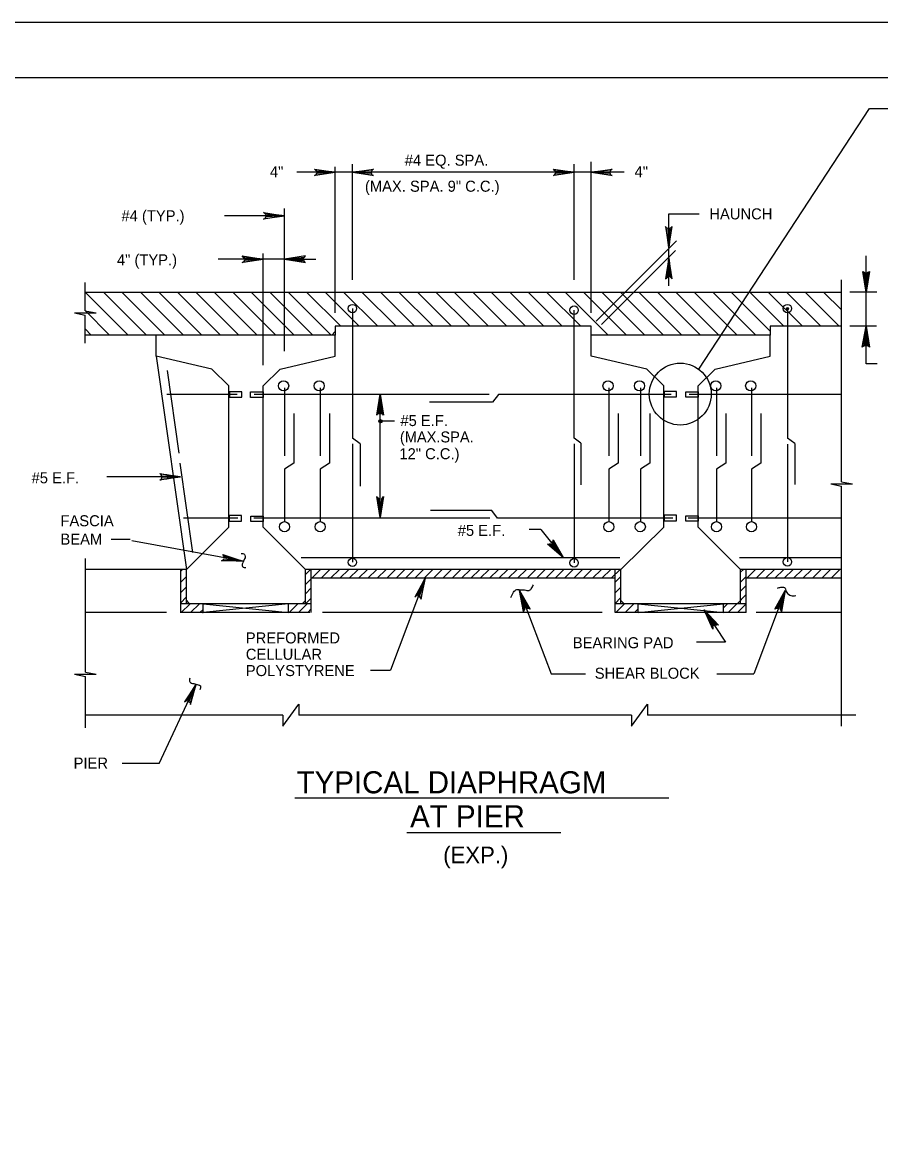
# Model space of a CAD drawing. Extents: x 639980 to 641204, y 298038 to 300414.
# Drawn here: x 640308.1 to 640541.7, y 300111.5 to 300413.8 of the extents above; entities that cross this region are included whole.
import ezdxf

# ---------------------------------------------------------------- set-up
doc = ezdxf.new("R2010")
doc.units = 0
doc.layers.add('2', color=7, linetype='Continuous')
doc.layers.add('PLT-BNDY', color=7, linetype='Continuous')

msp = doc.modelspace()

# ---------------------------------------------------------------- linework, layer by layer
at = {"layer": '2'}
for p, q in [((640020.31, 300398.78), (640806.31, 300398.78)), ((640492.16, 300319.42), (640538.64, 300390.32)), ((640538.64, 300390.32), (640544.27, 300390.32)), ((640462.88, 300334.72), (640462.88, 300375.82)), ((640397.93, 300372.97), (640382.84, 300372.97)), ((640393.28, 300334.72), (640393.28, 300374.47)), ((640397.93, 300343.72), (640397.93, 300375.22)), ((640458.23, 300372.97), (640397.93, 300372.97)), ((640458.23, 300343.72), (640458.23, 300375.22)), ((640471.84, 300372.97), (640458.23, 300372.97)), ((640379.46, 300361.16), (640363.14, 300361.16)), ((640379.46, 300324.33), (640379.46, 300363.17)), ((640484.03, 300361.72), (640492.28, 300361.72)), ((640484.03, 300352.42), (640484.03, 300361.72)), ((640464.27, 300332.5), (640486.13, 300354.37)), ((640465.74, 300331.57), (640485.83, 300351.67)), ((640484.03, 300342.07), (640484.03, 300352.27)), ((640379.46, 300349.33), (640361.39, 300349.33)), ((640373.63, 300320.53), (640373.63, 300350.89)), ((640379.48, 300349.33), (640387.94, 300349.33)), ((640537.71, 300340.42), (640537.71, 300350.23)), ((640325.18, 300335.32), (640325.18, 300342.97)), ((640530.98, 300288.82), (640530.98, 300343.72)), ((640325.18, 300340.42), (640530.98, 300340.42)), ((640325.18, 300340.42), (640325.18, 300340.42)), ((640325.18, 300340.42), (640325.18, 300340.42)), ((640325.18, 300340.42), (640336.88, 300328.72)), ((640330.21, 300340.42), (640341.91, 300328.72)), ((640335.23, 300340.42), (640346.93, 300328.72)), ((640340.25, 300340.42), (640351.95, 300328.72)), ((640345.28, 300340.42), (640356.98, 300328.72)), ((640350.3, 300340.42), (640362, 300328.72)), ((640355.32, 300340.42), (640367.02, 300328.72)), ((640360.35, 300340.42), (640372.05, 300328.72)), ((640365.37, 300340.42), (640377.07, 300328.72)), ((640370.39, 300340.42), (640382.09, 300328.72)), ((640375.42, 300340.42), (640387.12, 300328.72)), ((640380.44, 300340.42), (640392.14, 300328.72)), ((640385.46, 300340.42), (640394.76, 300331.12)), ((640390.49, 300340.42), (640399.79, 300331.12)), ((640395.51, 300340.42), (640404.81, 300331.12)), ((640400.53, 300340.42), (640409.83, 300331.12)), ((640405.56, 300340.42), (640414.86, 300331.12)), ((640410.58, 300340.42), (640419.88, 300331.12)), ((640415.6, 300340.42), (640424.9, 300331.12)), ((640420.63, 300340.42), (640429.93, 300331.12)), ((640425.65, 300340.42), (640434.95, 300331.12)), ((640430.67, 300340.42), (640439.97, 300331.12)), ((640435.7, 300340.42), (640445, 300331.12)), ((640440.72, 300340.42), (640450.02, 300331.12)), ((640445.74, 300340.42), (640455.04, 300331.12)), ((640450.76, 300340.42), (640460.06, 300331.12)), ((640455.79, 300340.42), (640467.49, 300328.72)), ((640460.81, 300340.42), (640472.51, 300328.72)), ((640465.83, 300340.42), (640477.53, 300328.72)), ((640470.86, 300340.42), (640482.56, 300328.72)), ((640475.88, 300340.42), (640487.58, 300328.72)), ((640480.9, 300340.42), (640492.6, 300328.72)), ((640485.93, 300340.42), (640497.63, 300328.72)), ((640490.95, 300340.42), (640502.65, 300328.72)), ((640495.97, 300340.42), (640507.67, 300328.72)), ((640501, 300340.42), (640511.63, 300329.78)), ((640506.02, 300340.42), (640515.32, 300331.12)), ((640511.04, 300340.42), (640520.34, 300331.12)), ((640516.07, 300340.42), (640525.37, 300331.12)), ((640521.09, 300340.42), (640530.39, 300331.12)), ((640526.11, 300340.42), (640530.98, 300335.55)), ((640540.64, 300340.42), (640533.24, 300340.42)), ((640537.71, 300331.12), (640537.71, 300340.42)), ((640322.33, 300334.72), (640328.18, 300334.72)), ((640322.33, 300334.72), (640325.18, 300334.12)), ((640325.18, 300335.39), (640331.86, 300328.72)), ((640325.18, 300335.32), (640328.18, 300334.72)), ((640325.18, 300326.47), (640325.18, 300334.12)), ((640397.93, 300335.92), (640397.93, 300300.67)), ((640458.23, 300300.67), (640458.23, 300335.47)), ((640516.28, 300335.92), (640516.28, 300300.67)), ((640462.88, 300331.12), (640393.28, 300331.12)), ((640393.28, 300331.12), (640393.28, 300328.72)), ((640462.88, 300328.72), (640462.88, 300331.12)), ((640530.98, 300331.12), (640511.63, 300331.12)), ((640511.63, 300331.12), (640511.63, 300328.72)), ((640540.5, 300331.12), (640533.24, 300331.12)), ((640537.71, 300320.86), (640537.71, 300331.12)), ((640325.18, 300330.37), (640326.84, 300328.72)), ((640393.28, 300328.72), (640325.18, 300328.72)), ((640344.53, 300323.02), (640344.53, 300328.72)), ((640392.31, 300328.72), (640393.28, 300329.69)), ((640393.28, 300328.87), (640393.28, 300328.72)), ((640393.28, 300323.02), (640393.28, 300328.72)), ((640462.88, 300323.02), (640462.88, 300328.72)), ((640511.63, 300328.72), (640462.88, 300328.72)), ((640511.63, 300328.87), (640511.63, 300328.72)), ((640511.63, 300323.02), (640511.63, 300328.72)), ((640359.68, 300319.42), (640344.53, 300323.02)), ((640344.53, 300323.02), (640352.78, 300264.97)), ((640378.28, 300319.42), (640393.28, 300323.02)), ((640478.03, 300319.42), (640462.88, 300323.02)), ((640496.63, 300319.42), (640511.63, 300323.02)), ((640347.53, 300319.12), (640350.68, 300296.62)), ((640364.33, 300314.92), (640359.68, 300319.42)), ((640373.63, 300314.92), (640378.28, 300319.42)), ((640482.68, 300314.92), (640478.03, 300319.42)), ((640491.98, 300314.92), (640496.63, 300319.42)), ((640540.72, 300320.86), (640537.71, 300320.86)), ((640366.58, 300312.52), (640347.42, 300312.52)), ((640364.33, 300276.52), (640364.33, 300314.92)), ((640435.18, 300312.52), (640371.23, 300312.52)), ((640373.63, 300276.52), (640373.63, 300314.92)), ((640379.46, 300314.39), (640379.46, 300295.86)), ((640389.17, 300314.39), (640389.17, 300295.86)), ((640405.51, 300279.08), (640405.51, 300312.68)), ((640437.68, 300312.52), (640436, 300310.45)), ((640484.63, 300312.52), (640437.68, 300312.52)), ((640467.72, 300314.39), (640467.72, 300295.86)), ((640476.28, 300314.39), (640476.28, 300295.86)), ((640482.68, 300276.52), (640482.68, 300314.92)), ((640530.98, 300312.52), (640489.58, 300312.52)), ((640491.98, 300276.52), (640491.98, 300314.92)), ((640497.03, 300314.39), (640497.03, 300295.86)), ((640506.55, 300314.39), (640506.55, 300295.86)), ((640436, 300310.45), (640418.93, 300310.45)), ((640382, 300307.36), (640382, 300293.9)), ((640391.7, 300307.36), (640391.7, 300293.9)), ((640470.26, 300307.36), (640470.26, 300293.9)), ((640478.82, 300307.36), (640478.82, 300293.9)), ((640499.57, 300307.36), (640499.57, 300293.9)), ((640509.09, 300307.36), (640509.09, 300293.9)), ((640405.51, 300305.35), (640409.41, 300305.35)), ((640400.02, 300299.16), (640397.93, 300300.67)), ((640460.05, 300299.35), (640458.23, 300300.67)), ((640518.27, 300299.22), (640516.28, 300300.67)), ((640397.93, 300299.15), (640397.93, 300266.92)), ((640400.02, 300299.16), (640400.02, 300287.67)), ((640458.23, 300299.15), (640458.23, 300266.77)), ((640460.05, 300299.35), (640460.05, 300287.95)), ((640516.28, 300299.01), (640516.28, 300267.07)), ((640518.27, 300299.22), (640518.27, 300288.08)), ((640350.98, 300293.92), (640354.43, 300269.62)), ((640382, 300293.9), (640379.46, 300292.29)), ((640379.46, 300292.29), (640379.46, 300277.95)), ((640391.7, 300293.9), (640389.17, 300292.29)), ((640389.17, 300292.29), (640389.17, 300277.95)), ((640470.26, 300293.9), (640467.72, 300292.29)), ((640467.72, 300292.29), (640467.72, 300277.95)), ((640478.82, 300293.9), (640476.28, 300292.29)), ((640476.28, 300292.29), (640476.28, 300277.95)), ((640499.57, 300293.9), (640497.03, 300292.29)), ((640497.03, 300292.29), (640497.03, 300277.95)), ((640509.09, 300293.9), (640506.55, 300292.29)), ((640506.55, 300292.29), (640506.55, 300277.95)), ((640351.13, 300290.17), (640331.09, 300290.17)), ((640528.13, 300288.22), (640533.98, 300288.22)), ((640528.13, 300288.22), (640530.98, 300287.62)), ((640530.98, 300288.82), (640533.98, 300288.22)), ((640530.98, 300222.37), (640530.98, 300287.62)), ((640435.85, 300281.03), (640419.2, 300281.03)), ((640437.38, 300278.92), (640435.85, 300281.03)), ((640366.73, 300278.92), (640351.98, 300278.92)), ((640352.78, 300264.97), (640364.33, 300276.52)), ((640435.32, 300278.92), (640371.08, 300278.92)), ((640373.63, 300276.52), (640385.18, 300264.97)), ((640485.08, 300278.92), (640437.38, 300278.92)), ((640470.98, 300264.97), (640482.68, 300276.52)), ((640530.98, 300278.92), (640489.28, 300278.92)), ((640491.98, 300276.52), (640503.53, 300264.97)), ((640337.43, 300273.16), (640332.27, 300273.16)), ((640449.19, 300275.81), (640446.04, 300275.81)), ((640449.19, 300275.81), (640455.38, 300268.12)), ((640368.13, 300267.28), (640337.88, 300272.77)), ((640325.33, 300237.07), (640325.33, 300268)), ((640470.68, 300268.12), (640383.98, 300268.12)), ((640530.98, 300268.12), (640503.23, 300268.12)), ((640352.78, 300264.97), (640325.33, 300264.97)), ((640351.22, 300264.52), (640351.71, 300265.01)), ((640351.22, 300253.27), (640351.22, 300264.97)), ((640352.78, 300255.67), (640352.78, 300264.97)), ((640385.18, 300263.62), (640386.56, 300265.01)), ((640385.18, 300255.67), (640385.18, 300264.97)), ((640470.98, 300264.97), (640385.18, 300264.97)), ((640385.18, 300264.91), (640385.24, 300264.97)), ((640385.18, 300264.97), (640385.18, 300264.97)), ((640386.74, 300253.27), (640386.74, 300264.97)), ((640386.74, 300264.97), (640386.74, 300264.97)), ((640386.89, 300262.57), (640389.29, 300264.97)), ((640389.43, 300262.57), (640391.83, 300264.97)), ((640391.98, 300262.57), (640394.38, 300264.97)), ((640394.53, 300262.57), (640396.93, 300264.97)), ((640397.07, 300262.57), (640399.47, 300264.97)), ((640399.62, 300262.57), (640402.02, 300264.97)), ((640402.16, 300262.57), (640404.56, 300264.97)), ((640404.71, 300262.57), (640407.11, 300264.97)), ((640407.25, 300262.57), (640409.65, 300264.97)), ((640409.8, 300262.57), (640412.2, 300264.97)), ((640412.34, 300262.57), (640414.74, 300264.97)), ((640414.89, 300262.57), (640417.29, 300264.97)), ((640417.44, 300262.57), (640419.84, 300264.97)), ((640419.98, 300262.57), (640422.38, 300264.97)), ((640422.53, 300262.57), (640424.93, 300264.97)), ((640425.07, 300262.57), (640427.47, 300264.97)), ((640427.62, 300262.57), (640430.02, 300264.97)), ((640430.16, 300262.57), (640432.56, 300264.97)), ((640432.71, 300262.57), (640435.11, 300264.97)), ((640435.25, 300262.57), (640437.65, 300264.97)), ((640437.8, 300262.57), (640440.2, 300264.97)), ((640440.35, 300262.57), (640442.75, 300264.97)), ((640442.89, 300262.57), (640445.29, 300264.97)), ((640445.44, 300262.57), (640447.84, 300264.97)), ((640447.98, 300262.57), (640450.38, 300264.97)), ((640450.53, 300262.57), (640452.93, 300264.97)), ((640453.07, 300262.57), (640455.47, 300264.97)), ((640455.62, 300262.57), (640458.02, 300264.97)), ((640458.16, 300262.57), (640460.56, 300264.97)), ((640460.71, 300262.57), (640463.11, 300264.97)), ((640463.26, 300262.57), (640465.66, 300264.97)), ((640465.8, 300262.57), (640468.2, 300264.97)), ((640468.35, 300262.57), (640470.77, 300264.99)), ((640469.42, 300253.27), (640469.42, 300264.97)), ((640470.98, 300255.67), (640470.98, 300264.97)), ((640503.53, 300255.67), (640503.53, 300264.97)), ((640530.98, 300264.97), (640503.53, 300264.97)), ((640503.54, 300264.21), (640504.3, 300264.97)), ((640505.09, 300253.27), (640505.09, 300264.97)), ((640505.09, 300264.97), (640505.09, 300264.97)), ((640505.24, 300262.57), (640507.64, 300264.97)), ((640507.78, 300262.57), (640510.18, 300264.97)), ((640510.33, 300262.57), (640512.73, 300264.97)), ((640512.88, 300262.57), (640515.28, 300264.97)), ((640515.42, 300262.57), (640517.82, 300264.97)), ((640517.97, 300262.57), (640520.37, 300264.97)), ((640520.51, 300262.57), (640522.91, 300264.97)), ((640523.06, 300262.57), (640525.46, 300264.97)), ((640525.6, 300262.57), (640528, 300264.97)), ((640528.15, 300262.57), (640530.55, 300264.97)), ((640351.17, 300261.45), (640352.75, 300263.03)), ((640386.73, 300262.44), (640385.15, 300260.87)), ((640469.42, 300262.57), (640386.74, 300262.57)), ((640417.72, 300262.57), (640408.29, 300237.57)), ((640469.4, 300261.52), (640470.94, 300263.06)), ((640505.06, 300263.07), (640503.49, 300261.51)), ((640530.98, 300262.57), (640505.09, 300262.57)), ((640530.69, 300262.57), (640530.98, 300262.85)), ((640351.17, 300258.63), (640352.7, 300260.16)), ((640385.22, 300258.49), (640386.61, 300259.88)), ((640443.43, 300259.27), (640451.98, 300236.62)), ((640469.42, 300258.66), (640470.94, 300260.18)), ((640505.01, 300258.04), (640502.63, 300255.67)), ((640505.06, 300260.61), (640503.49, 300259.04)), ((640515.68, 300259.27), (640507.13, 300236.62)), ((640351.22, 300255.94), (640352.7, 300257.43)), ((640386.74, 300255.67), (640351.22, 300255.67)), ((640351.22, 300255.67), (640351.22, 300255.67)), ((640351.37, 300253.27), (640353.77, 300255.67)), ((640352.78, 300256.57), (640353.53, 300255.67)), ((640353.91, 300253.27), (640356.31, 300255.67)), ((640357.28, 300253.27), (640357.28, 300255.67)), ((640357.28, 300255.67), (640380.53, 300253.27)), ((640380.53, 300255.67), (640357.28, 300253.27)), ((640380.53, 300253.27), (640380.53, 300255.67)), ((640380.53, 300255.67), (640380.53, 300255.67)), ((640380.68, 300253.27), (640383.08, 300255.67)), ((640383.22, 300253.27), (640385.62, 300255.67)), ((640385.18, 300256.57), (640384.28, 300255.67)), ((640386.73, 300257.17), (640385.2, 300255.64)), ((640469.42, 300255.77), (640470.89, 300257.24)), ((640505.09, 300255.67), (640469.42, 300255.67)), ((640469.42, 300255.67), (640469.42, 300255.67)), ((640469.57, 300253.27), (640471.97, 300255.67)), ((640470.98, 300256.57), (640471.88, 300255.67)), ((640472.11, 300253.27), (640474.51, 300255.67)), ((640475.63, 300253.27), (640475.63, 300255.67)), ((640475.63, 300255.67), (640498.88, 300253.27)), ((640475.63, 300253.27), (640498.88, 300255.67)), ((640498.88, 300253.27), (640498.88, 300255.67)), ((640498.88, 300255.51), (640499.03, 300255.67)), ((640498.88, 300254.55), (640500, 300255.67)), ((640500.15, 300253.27), (640502.55, 300255.67)), ((640502.69, 300253.27), (640505.09, 300255.67)), ((640505.09, 300255.67), (640505.09, 300255.67)), ((640347.34, 300253.27), (640325.33, 300253.27)), ((640386.38, 300253.27), (640351.11, 300253.27)), ((640356.46, 300253.27), (640357.28, 300254.09)), ((640357.17, 300253.27), (640357.28, 300253.38)), ((640357.23, 300253.27), (640357.28, 300253.32)), ((640385.77, 300253.27), (640386.74, 300254.24)), ((640465.91, 300253.27), (640389.8, 300253.27)), ((640505.09, 300253.27), (640469.42, 300253.27)), ((640474.66, 300253.27), (640475.63, 300254.24)), ((640493.63, 300254.02), (640499.48, 300245.17)), ((640530.98, 300253.27), (640507.74, 300253.27)), ((640499.48, 300245.17), (640491.55, 300245.17)), ((640325.33, 300237.07), (640328.18, 300236.47)), ((640402.83, 300237.57), (640408.29, 300237.57)), ((640322.33, 300236.47), (640328.18, 300236.47)), ((640322.33, 300236.47), (640325.33, 300235.87)), ((640325.33, 300221.92), (640325.33, 300235.87)), ((640345.31, 300212.21), (640355.42, 300233.78)), ((640451.98, 300236.62), (640461.39, 300236.62)), ((640497.05, 300236.62), (640507.13, 300236.62)), ((640379.03, 300222.37), (640383.38, 300228.37)), ((640383.38, 300228.37), (640383.38, 300225.37)), ((640473.83, 300222.37), (640478.18, 300228.37)), ((640478.18, 300228.37), (640478.18, 300225.37)), ((640379.03, 300225.37), (640325.33, 300225.37)), ((640379.03, 300225.37), (640379.03, 300222.37)), ((640473.83, 300225.37), (640383.38, 300225.37)), ((640473.83, 300225.37), (640473.83, 300222.37)), ((640534.88, 300225.37), (640478.18, 300225.37)), ((640345.31, 300212.21), (640335.26, 300212.21)), ((640382.25, 300202.86), (640484, 300202.86)), ((640412.75, 300193.49), (640454.63, 300193.49))]:
    msp.add_line(p, q, dxfattribs=at)
for points in [[(640387.88, 300373.57), (640388.18, 300373.27), (640393.28, 300372.97), (640387.88, 300373.57), (640387.58, 300373.87), (640393.28, 300372.97), (640388.18, 300372.67), (640387.88, 300372.22), (640393.28, 300372.97), (640387.58, 300372.07), (640387.88, 300372.22)], [(640403.33, 300372.22), (640403.18, 300372.67), (640397.93, 300372.97), (640403.33, 300372.22), (640403.63, 300372.07), (640397.93, 300372.97), (640403.18, 300373.12), (640403.33, 300373.57), (640397.93, 300372.97), (640403.63, 300373.87), (640403.33, 300373.57)], [(640452.83, 300373.57), (640453.13, 300373.27), (640458.23, 300372.97), (640452.83, 300373.57), (640452.68, 300373.87), (640458.23, 300372.97), (640453.13, 300372.67), (640452.83, 300372.22), (640458.23, 300372.97), (640452.68, 300372.07), (640452.83, 300372.22)], [(640468.28, 300372.22), (640468.13, 300372.67), (640462.88, 300372.97), (640468.28, 300372.22), (640468.58, 300372.07), (640462.88, 300372.97), (640468.13, 300373.12), (640468.28, 300373.57), (640462.88, 300372.97), (640468.58, 300373.87), (640468.28, 300373.57)], [(640374.06, 300361.76), (640374.36, 300361.46), (640379.46, 300361.16), (640374.06, 300361.76), (640373.76, 300362.06), (640379.46, 300361.16), (640374.36, 300360.86), (640374.06, 300360.41), (640379.46, 300361.16), (640373.76, 300360.26), (640374.06, 300360.41)], [(640483.28, 300357.97), (640483.73, 300357.82), (640484.03, 300352.57), (640483.28, 300357.97), (640483.13, 300358.27), (640484.03, 300352.57), (640484.33, 300357.82), (640484.63, 300357.97), (640484.03, 300352.57), (640484.93, 300358.27), (640484.63, 300357.97)], [(640368.23, 300349.93), (640368.53, 300349.63), (640373.63, 300349.33), (640368.23, 300349.93), (640367.93, 300350.23), (640373.63, 300349.33), (640368.53, 300349.03), (640368.23, 300348.58), (640373.63, 300349.33), (640367.93, 300348.43), (640368.23, 300348.58)], [(640384.88, 300349.93), (640384.58, 300349.63), (640379.48, 300349.33), (640384.88, 300349.93), (640385.18, 300350.23), (640379.48, 300349.33), (640384.58, 300349.03), (640384.88, 300348.58), (640379.48, 300349.33), (640385.18, 300348.43), (640384.88, 300348.58)], [(640484.63, 300344.32), (640484.33, 300344.62), (640484.03, 300349.72), (640484.63, 300344.32), (640484.93, 300344.02), (640484.03, 300349.72), (640483.73, 300344.62), (640483.43, 300344.32), (640484.03, 300349.72), (640483.13, 300344.02), (640483.43, 300344.32)], [(640538.31, 300345.82), (640537.86, 300345.52), (640537.71, 300340.42), (640538.31, 300345.82), (640538.61, 300345.97), (640537.71, 300340.42), (640537.41, 300345.52), (640536.96, 300345.82), (640537.71, 300340.42), (640536.81, 300345.97), (640536.96, 300345.82)], [(640536.96, 300325.72), (640537.41, 300325.87), (640537.71, 300331.12), (640536.96, 300325.72), (640536.66, 300325.42), (640537.71, 300331.12), (640537.86, 300325.87), (640538.31, 300325.72), (640537.71, 300331.12), (640538.61, 300325.42), (640538.31, 300325.72)], [(640404.76, 300307.28), (640405.21, 300307.43), (640405.51, 300312.68), (640404.76, 300307.28), (640404.61, 300306.98), (640405.51, 300312.68), (640405.66, 300307.43), (640406.11, 300307.28), (640405.51, 300312.68), (640406.41, 300306.98), (640406.11, 300307.28)], [(640345.73, 300290.92), (640346.03, 300290.47), (640351.13, 300290.17), (640345.73, 300290.92), (640345.58, 300291.07), (640351.13, 300290.17), (640346.03, 300290.02), (640345.88, 300289.57), (640351.13, 300290.17), (640345.58, 300289.27), (640345.88, 300289.57)], [(640347.53, 300290.62), (640347.68, 300290.47), (640351.13, 300290.17), (640347.53, 300290.62), (640347.38, 300290.77), (640351.13, 300290.17), (640347.68, 300290.02), (640347.53, 300289.72), (640351.13, 300290.17), (640347.38, 300289.57), (640347.53, 300289.72)], [(640406.11, 300284.48), (640405.81, 300284.18), (640405.51, 300279.08), (640406.11, 300284.48), (640406.41, 300284.78), (640405.51, 300279.08), (640405.21, 300284.18), (640404.76, 300284.48), (640405.51, 300279.08), (640404.61, 300284.78), (640404.76, 300284.48)], [(640452.53, 300272.62), (640452.23, 300272.32), (640455.38, 300268.12), (640452.53, 300272.62), (640452.53, 300273.07), (640455.38, 300268.12), (640451.93, 300271.87), (640451.48, 300271.87), (640455.38, 300268.12), (640451.03, 300271.87), (640451.48, 300271.87)], [(640362.89, 300268.72), (640362.99, 300268.4), (640368.13, 300267.28), (640362.89, 300268.72), (640362.64, 300269.07), (640368.13, 300267.28), (640362.89, 300267.81), (640362.7, 300267.54), (640368.13, 300267.28), (640362.35, 300267.29), (640362.7, 300267.54)], [(640416.52, 300257.17), (640416.22, 300257.62), (640417.72, 300262.57), (640416.52, 300257.17), (640416.67, 300256.87), (640417.72, 300262.57), (640415.62, 300257.77), (640415.32, 300257.77), (640417.72, 300262.57), (640414.87, 300257.47), (640415.32, 300257.77)], [(640444.63, 300253.87), (640444.93, 300254.32), (640443.43, 300259.27), (640444.63, 300253.87), (640444.48, 300253.57), (640443.43, 300259.27), (640445.53, 300254.47), (640445.83, 300254.47), (640443.43, 300259.27), (640446.28, 300254.17), (640445.83, 300254.47)], [(640513.28, 300254.47), (640513.58, 300254.47), (640515.68, 300259.27), (640513.28, 300254.47), (640512.83, 300254.17), (640515.68, 300259.27), (640514.18, 300254.32), (640514.48, 300254.02), (640515.68, 300259.27), (640514.63, 300253.57), (640514.48, 300254.02)], [(640496.03, 300249.22), (640496.18, 300249.52), (640493.63, 300254.02), (640496.03, 300249.22), (640496.03, 300248.77), (640493.63, 300254.02), (640496.63, 300249.82), (640497.08, 300249.97), (640493.63, 300254.02), (640497.53, 300249.82), (640497.08, 300249.97)], [(640353.77, 300228.68), (640353.47, 300228.98), (640355.42, 300233.78), (640353.77, 300228.68), (640353.92, 300228.23), (640355.42, 300233.78), (640353.02, 300229.28), (640352.57, 300229.13), (640355.42, 300233.78), (640352.27, 300228.98), (640352.57, 300229.13)]]:
    msp.add_lwpolyline(points, dxfattribs=at)
for points in [[(640364.47, 300311.83), (640367.85, 300311.83), (640367.85, 300313.32), (640364.47, 300313.32)], [(640373.61, 300311.78), (640370.23, 300311.78), (640370.23, 300313.27), (640373.61, 300313.27)], [(640482.72, 300311.93), (640486.11, 300311.93), (640486.11, 300313.41), (640482.72, 300313.41)], [(640492.01, 300311.82), (640488.63, 300311.82), (640488.63, 300313.3), (640492.01, 300313.3)], [(640364.41, 300278.15), (640367.79, 300278.15), (640367.79, 300279.63), (640364.41, 300279.63)], [(640373.64, 300278), (640370.26, 300278), (640370.26, 300279.48), (640373.64, 300279.48)], [(640482.73, 300278.21), (640486.11, 300278.21), (640486.11, 300279.7), (640482.73, 300279.7)], [(640491.99, 300278.11), (640488.61, 300278.11), (640488.61, 300279.59), (640491.99, 300279.59)]]:
    msp.add_lwpolyline(points, close=True, dxfattribs=at)
for centre, radius in [((640397.93, 300335.92), 1.15), ((640458.23, 300335.47), 1.15), ((640516.28, 300335.92), 1.15), ((640516.29, 300335.88), 0.29), ((640487.12, 300312.67), 8.42), ((640379.21, 300314.9), 1.38), ((640388.91, 300314.9), 1.38), ((640467.47, 300314.9), 1.38), ((640476.03, 300314.9), 1.38), ((640496.78, 300314.9), 1.38), ((640506.29, 300314.9), 1.38), ((640405.56, 300305.31), 0.434), ((640405.7, 300305.17), 0.273), ((640379.43, 300276.61), 1.38), ((640389.14, 300276.61), 1.38), ((640467.69, 300276.61), 1.38), ((640476.25, 300276.61), 1.38), ((640497, 300276.61), 1.38), ((640506.52, 300276.61), 1.38), ((640397.93, 300266.92), 1.15), ((640458.23, 300266.77), 1.15), ((640516.28, 300267.07), 1.15)]:
    msp.add_circle(centre, radius, dxfattribs=at)
for points in [[(640367.69, 300269.32), (640368.43, 300269.21), (640368.68, 300268.86), (640368.71, 300268.1), (640368.49, 300267.68), (640368.25, 300267.11), (640367.98, 300266.39), (640368.04, 300265.78), (640368.46, 300265.56), (640368.9, 300265.49)], [(640441.03, 300257.32), (640441.78, 300258.82), (640442.68, 300259.57), (640443.73, 300259.42), (640444.78, 300259.42), (640445.98, 300259.27), (640446.58, 300259.72), (640447.18, 300260.77)], [(640513.58, 300259.87), (640514.48, 300260.17), (640515.68, 300259.87), (640515.83, 300259.27), (640516.58, 300258.22), (640517.93, 300257.77), (640518.53, 300257.92)], [(640353.72, 300235.44), (640353.57, 300234.84), (640353.72, 300234.39), (640354.17, 300234.09), (640354.77, 300233.94), (640355.37, 300233.79), (640355.97, 300233.64), (640356.57, 300233.34), (640356.57, 300232.74), (640356.42, 300232.29)]]:
    msp.add_spline(points, degree=3, dxfattribs=at)
at = {"layer": 'PLT-BNDY'}
msp.add_lwpolyline([(639980.31, 300413.78), (640821.31, 300413.78), (640821.31, 299819.78), (639980.31, 299819.78)], close=True, dxfattribs=at)

# ---------------------------------------------------------------- texts
at = {"layer": '2'}
for s, height, p in [('#4 EQ. SPA. ', 2.9987, (640412.17, 300374.77)), ('4"', 2.999, (640375.49, 300371.64)), ('4"', 2.999, (640474.7, 300371.64)), ('(MAX. SPA. 9" C.C.)', 2.9987, (640401.34, 300367.69)), ('#4 (TYP.)', 2.999, (640335.09, 300359.65)), ('HAUNCH', 2.999, (640495.04, 300360.17)), ('4" (TYP.)', 2.999, (640333.87, 300347.67)), ('#5 E.F.', 2.999, (640410.99, 300303.97)), ('(MAX.SPA.', 2.969, (640410.85, 300299.53)), ('12" C.C.)', 2.999, (640410.71, 300294.95)), ('#5 E.F.', 2.999, (640310.65, 300288.41)), ('FASCIA', 2.999, (640318.5, 300276.73)), ('#5 E.F.', 2.999, (640426.59, 300274.11)), ('BEAM', 2.999, (640318.5, 300271.73)), ('PREFORMED', 2.999, (640368.93, 300244.87)), ('BEARING PAD', 2.9988, (640457.89, 300243.56)), ('CELLULAR', 2.999, (640368.93, 300240.43)), ('POLYSTYRENE', 2.9988, (640368.93, 300235.99)), ('SHEAR BLOCK', 2.9988, (640463.87, 300235.27)), ('PIER', 2.999, (640322.08, 300210.83)), ('TYPICAL DIAPHRAGM', 6, (640382.75, 300204.11)), ('AT PIER', 6, (640413.63, 300194.86)), ('(EXP.)', 4.5, (640422.63, 300185.11))]:
    msp.add_text(s, height=height, dxfattribs=at).set_placement(p)

doc.saveas('drawing.dxf')
